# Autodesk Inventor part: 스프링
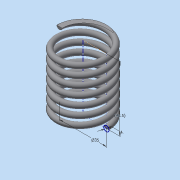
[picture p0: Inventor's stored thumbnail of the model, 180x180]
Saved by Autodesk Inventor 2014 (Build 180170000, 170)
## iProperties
Created: 2014-12
Part Number: 스프링
Material: 일반
Document SubType Name: Modeling
Designer: user
Density: 1 g/cm^3
Appearance: 기본값
Author: user
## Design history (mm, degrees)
sketch "스케치1"
  geometry: L1 (0, 0)-(17.5, 0); L2 (17.5, 0)-(17.5, 62.5); L3 (17.5, 62.5)-(0, 62.5); L4 (0, 62.5)-(0, 0); C1 r 2 at (17.5, 0)
  constraints: 8 end point, 2 parallel, 1 centre point, 1 coincident, 1 horizontal, 1 perpendicular
  dimensions: "d0" = 35 diameter of L2 L4; "d1" = 62.5 distance between parallel lines of L1 L3 (derived); "d2" = 4 diameter of C1
feature "코일1" sketch "스케치1" pitch "d3" = 10; turns "d5" = 7.5; dims "d4" = 62.5 (= d1), "d6" = 0, angle "d7" = 90 deg, angle "d8" = 90 deg, "d9" = 0, "d10" = 0
sketch "스케치3"
  geometry: L1 (-19.5, 0)-(-15.5, 0) reference; 1 further point
  constraints: 1 horizontal alignment
extrude "돌출1" cut sketch "스케치3" stored distance "d11" = 10; taper "d12" = 0 deg
node "작업 평면1"
sketch "스케치4"
  geometry: L1 (-4, 0)-(0, 0) reference; 1 further point
  constraints: 1 horizontal alignment
extrude "돌출2" cut sketch "스케치4" stored distance "d13" = 10; taper "d14" = 0 deg
node "솔리드1"
node "절단 모서리 투영2"
node "절단 모서리 투영3"
